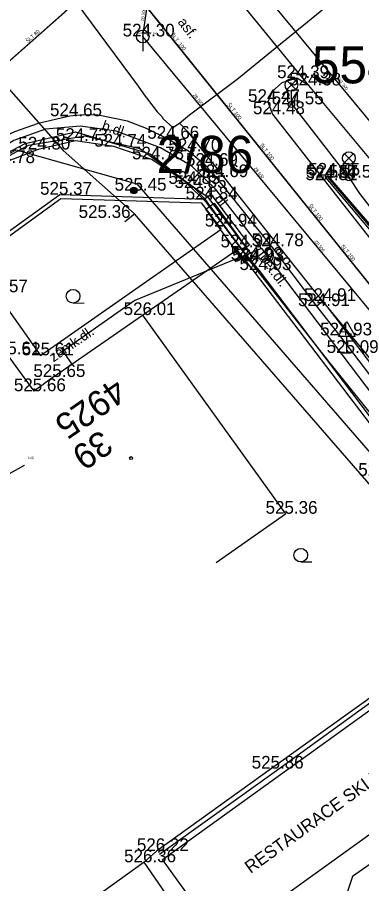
# Model space of a CAD drawing. Extents: x -668867 to -667827, y -1131943 to -1131019.
# Drawn here: x -668677.7 to -668657.4, y -1131290.2 to -1131239 of the extents above; entities that cross this region are included whole.
import ezdxf

# ---------------------------------------------------------------- set-up
doc = ezdxf.new("R2010")
doc.units = 0
for name, color, linetype in [('G_Bod_tecka', 7, 'Continuous'), ('G_Bod_vyska', 7, 'Continuous'), ('G_Budovy-znacky', 7, 'Continuous'), ('G_Budovy_Objekty', 7, 'Continuous'), ('G_Budovy_vstupy', 7, 'Continuous'), ('G_Cesty_Schody', 7, 'Continuous'), ('G_Cisla_orientacni', 7, 'Continuous'), ('G_Cisla_popisna', 7, 'Continuous'), ('G_Objekty_dopravni', 7, 'Continuous'), ('G_Objekty_technicke', 7, 'Continuous'), ('G_Plochy_zpevnene', 7, 'Continuous'), ('G_Ploty', 7, 'Continuous'), ('G_Ploty_vstupy', 7, 'Continuous'), ('G_Popisy_povrchu', 7, 'Continuous'), ('G_Poznamky_odkaz', 7, 'Continuous'), ('G_Site-kanalizace', 7, 'Continuous'), ('G_Site-Sloupy', 7, 'Continuous'), ('G_Z_CHRANICKA-TEPLOVOD_kotovane', 7, 'Continuous'), ('G_Z_ELsilove_podz_kotovane', 7, 'Continuous'), ('G_Z_ELsilove_zrusene', 7, 'Continuous'), ('G_Z_KANAL_podz_kotovane', 7, 'Continuous'), ('G_Z_KANAL_podz_priblizne', 7, 'Continuous'), ('G_Z_PLYNY_podz_geodeticky', 7, 'Continuous'), ('G_Z_SPOJE_podz_geodeticky', 7, 'Continuous'), ('G_Z_SPOJE_podz_kotovane', 7, 'Continuous'), ('G_Z_SPOJE_podz_priblizne', 7, 'Continuous'), ('G_Z_VODA_podz_kotovane', 7, 'Continuous'), ('G_Zabradli_Svodidla', 7, 'Continuous'), ('G_Zelen-Znacky', 7, 'Continuous'), ('Vrstva 1', 7, 'Continuous'), ('Vrstva 10', 7, 'Continuous'), ('Vrstva 12', 7, 'Continuous'), ('Vrstva 17', 7, 'Continuous'), ('Vrstva 2', 7, 'Continuous'), ('Vrstva 25', 7, 'Continuous'), ('Vrstva 26', 7, 'Continuous'), ('Vrstva 3', 7, 'Continuous'), ('Vrstva 4', 7, 'Continuous'), ('Vrstva 8', 7, 'Continuous')]:
    doc.layers.add(name, color=color, linetype=linetype)

msp = doc.modelspace()

# ---------------------------------------------------------------- linework, layer by layer
at = {"layer": 'G_Bod_tecka'}
for p, q in [((-668670.28, -1131240.15), (-668670.28, -1131240.15)), ((-668661.18, -1131242.61), (-668661.18, -1131242.61)), ((-668660.47, -1131243.04), (-668660.47, -1131243.04)), ((-668662.9, -1131244.02), (-668662.9, -1131244.02)), ((-668661.5, -1131244.16), (-668661.5, -1131244.16)), ((-668674.59, -1131244.86), (-668674.59, -1131244.86)), ((-668662.61, -1131244.74), (-668662.61, -1131244.74)), ((-668674.25, -1131246.32), (-668674.25, -1131246.32)), ((-668668.82, -1131246.19), (-668668.82, -1131246.19)), ((-668676.45, -1131246.83), (-668676.45, -1131246.83)), ((-668671.98, -1131246.66), (-668671.98, -1131246.66)), ((-668667.58, -1131246.93), (-668667.58, -1131246.93)), ((-668669.75, -1131247.41), (-668669.75, -1131247.41)), ((-668666.55, -1131247.79), (-668666.55, -1131247.79)), ((-668665.94, -1131248.46), (-668665.94, -1131248.46)), ((-668659.47, -1131248.5), (-668659.47, -1131248.5)), ((-668659.35, -1131248.37), (-668659.35, -1131248.37)), ((-668658.11, -1131248.49), (-668658.11, -1131248.49)), ((-668667.6, -1131248.86), (-668667.6, -1131248.86)), ((-668659.57, -1131248.64), (-668659.57, -1131248.64)), ((-668675.18, -1131249.5), (-668675.18, -1131249.5)), ((-668670.78, -1131249.26), (-668670.78, -1131249.26)), ((-668667.24, -1131249.1), (-668667.24, -1131249.1)), ((-668666.58, -1131249.78), (-668666.58, -1131249.78)), ((-668672.89, -1131250.87), (-668672.89, -1131250.87)), ((-668665.45, -1131251.38), (-668665.45, -1131251.38)), ((-668664.52, -1131252.61), (-668664.52, -1131252.61)), ((-668662.68, -1131252.54), (-668662.68, -1131252.54)), ((-668663.93, -1131253.35), (-668663.93, -1131253.35)), ((-668663.83, -1131253.44), (-668663.83, -1131253.44)), ((-668663.4, -1131253.95), (-668663.4, -1131253.95)), ((-668660.01, -1131256.08), (-668660.01, -1131256.08)), ((-668659.65, -1131255.78), (-668659.65, -1131255.78)), ((-668670.27, -1131256.61), (-668670.27, -1131256.61)), ((-668658.64, -1131257.81), (-668658.64, -1131257.81)), ((-668676.31, -1131258.99), (-668676.31, -1131258.99)), ((-668658.23, -1131258.85), (-668658.23, -1131258.85)), ((-668675.56, -1131260.27), (-668675.56, -1131260.27)), ((-668676.7, -1131261.11), (-668676.7, -1131261.11)), ((-668661.86, -1131268.35), (-668661.86, -1131268.35)), ((-668662.67, -1131283.41), (-668662.67, -1131283.41)), ((-668669.46, -1131288.28), (-668669.46, -1131288.28)), ((-668670.2, -1131288.94), (-668670.2, -1131288.94))]:
    msp.add_line(p, q, dxfattribs=at)
at = {"layer": 'G_Budovy-znacky'}
msp.add_circle((-668670.97, -1131265.061), 0.0875, dxfattribs=at)
at = {"layer": 'G_Budovy_Objekty'}
for p, q in [((-668675.56, -1131260.27), (-668670.3, -1131256.61)), ((-668670.3, -1131256.61), (-668661.86, -1131268.35)), ((-668676.7, -1131261.11), (-668678.28, -1131258.93)), ((-668665.94, -1131271.23), (-668661.86, -1131268.35)), ((-668669.11, -1131288.77), (-668652.01, -1131276.45)), ((-668649.65, -1131282.11), (-668665.63, -1131293.6)), ((-668670.2, -1131288.94), (-668673.43, -1131291.26)), ((-668667.36, -1131293.06), (-668670.2, -1131288.94)), ((-668666.2, -1131292.8), (-668669.11, -1131288.77))]:
    msp.add_line(p, q, dxfattribs=at)
at = {"layer": 'G_Budovy_vstupy'}
msp.add_line((-668675.56, -1131260.27), (-668676.7, -1131261.11), dxfattribs=at)
at = {"layer": 'G_Cesty_Schody'}
for p, q in [((-668660.47, -1131243.04), (-668676.96, -1131222.83)), ((-668666.55, -1131247.79), (-668667.6, -1131248.86)), ((-668662.68, -1131252.54), (-668663.83, -1131253.44)), ((-668659.65, -1131255.78), (-668660.01, -1131256.08))]:
    msp.add_line(p, q, dxfattribs=at)
msp.add_lwpolyline([(-668659.65, -1131255.78), (-668647.48, -1131271.71), (-668624, -1131302.71)], dxfattribs=at)
at = {"layer": 'G_Objekty_dopravni'}
for p, q in [((-668658.73, -1131257.85), (-668658.23, -1131257)), ((-668658.23, -1131257), (-668657.73, -1131257.85)), ((-668658.73, -1131257.85), (-668657.73, -1131257.85)), ((-668658.23, -1131258.85), (-668658.23, -1131257.85)), ((-668658.48, -1131258.85), (-668657.98, -1131258.85))]:
    msp.add_line(p, q, dxfattribs=at)
at = {"layer": 'G_Objekty_technicke'}
for p, q in [((-668661.765, -1131242.745), (-668661.235, -1131243.275)), ((-668661.765, -1131243.275), (-668661.235, -1131242.745)), ((-668661.5, -1131244.16), (-668661.5, -1131243.385)), ((-668658.375, -1131247.075), (-668657.845, -1131247.605)), ((-668658.375, -1131247.605), (-668657.845, -1131247.075)), ((-668658.11, -1131248.49), (-668658.11, -1131247.715))]:
    msp.add_line(p, q, dxfattribs=at)
for centre, radius in [((-668661.5, -1131243.01), 0.375), ((-668661.5, -1131244.16), 0.19), ((-668661.5, -1131244.16), 0.05), ((-668658.11, -1131247.34), 0.375), ((-668658.11, -1131248.49), 0.19), ((-668658.11, -1131248.49), 0.05)]:
    msp.add_circle(centre, radius, dxfattribs=at)
at = {"layer": 'G_Plochy_zpevnene'}
for p, q in [((-668659.47, -1131248.5), (-668659.57, -1131248.64)), ((-668659.47, -1131248.5), (-668651.37, -1131258.14)), ((-668659.57, -1131248.64), (-668656.1, -1131253.06)), ((-668670.3, -1131256.61), (-668664.72, -1131252.76))]:
    msp.add_line(p, q, dxfattribs=at)
for points in [[(-668660.47, -1131243.04), (-668661.18, -1131242.61), (-668662.06, -1131242.89), (-668662.63, -1131243.4), (-668662.9, -1131244.02), (-668662.61, -1131244.74), (-668659.57, -1131248.64)], [(-668656.04, -1131248.37), (-668660.47, -1131243.04)], [(-668674.59, -1131244.86), (-668676.45, -1131245.3), (-668677.86, -1131245.78), (-668679.91, -1131246.72), (-668681.77, -1131247.93), (-668682.93, -1131248.83)], [(-668665.94, -1131248.46), (-668666.55, -1131247.79), (-668667.58, -1131246.93), (-668668.82, -1131246.19), (-668670.05, -1131245.58), (-668671.19, -1131245.15), (-668672.91, -1131244.8), (-668673.76, -1131244.77), (-668674.59, -1131244.86)], [(-668674.25, -1131246.32), (-668676.45, -1131246.83), (-668678.55, -1131247.63), (-668680.81, -1131249.06), (-668681.77, -1131247.93)], [(-668666.58, -1131249.78), (-668667.24, -1131249.1), (-668667.6, -1131248.86), (-668669.75, -1131247.41), (-668671.98, -1131246.66), (-668674.25, -1131246.32)], [(-668662.68, -1131252.54), (-668665.94, -1131248.46)], [(-668659.35, -1131248.37), (-668659.47, -1131248.5)], [(-668651.07, -1131257.98), (-668659.35, -1131248.37)], [(-668676.31, -1131258.99), (-668665.65, -1131251.53)], [(-668658.64, -1131257.81), (-668660.01, -1131256.08), (-668662.68, -1131252.54)], [(-668681.68, -1131257.15), (-668678.97, -1131255.26), (-668676.31, -1131258.99)], [(-668633.58, -1131290.68), (-668658.64, -1131257.81)]]:
    msp.add_lwpolyline(points, dxfattribs=at)
at = {"layer": 'G_Ploty'}
for p, q in [((-668675.18, -1131249.5), (-668683.04, -1131255.19)), ((-668666.58, -1131249.78), (-668675.18, -1131249.5)), ((-668682.91, -1131255.37), (-668675.11, -1131249.72)), ((-668675.11, -1131249.72), (-668666.83, -1131249.97)), ((-668666.83, -1131249.97), (-668665.65, -1131251.53)), ((-668665.45, -1131251.38), (-668666.58, -1131249.78)), ((-668664.72, -1131252.76), (-668663.64, -1131254.14)), ((-668663.64, -1131254.14), (-668650.39, -1131271.57)), ((-668648.9, -1131273.5), (-668662.67, -1131283.41)), ((-668662.52, -1131283.61), (-668649.63, -1131274.28)), ((-668662.67, -1131283.41), (-668669.46, -1131288.28)), ((-668669.29, -1131288.47), (-668662.52, -1131283.61))]:
    msp.add_line(p, q, dxfattribs=at)
for points in [[(-668663.4, -1131253.95), (-668663.83, -1131253.44), (-668663.9, -1131253.35), (-668664.52, -1131252.61)], [(-668663.4, -1131253.95), (-668663.64, -1131254.14)], [(-668651.91, -1131269.15), (-668663.4, -1131253.95)]]:
    msp.add_lwpolyline(points, dxfattribs=at)
at = {"layer": 'G_Ploty_vstupy'}
for p, q in [((-668664.52, -1131252.61), (-668665.45, -1131251.38)), ((-668669.46, -1131288.28), (-668670.2, -1131288.94))]:
    msp.add_line(p, q, dxfattribs=at)
at = {"layer": 'G_Site-kanalizace'}
msp.add_line((-668670.28, -1131239.775), (-668670.28, -1131241.025), dxfattribs=at)
msp.add_circle((-668670.28, -1131240.15), 0.375, dxfattribs=at)
at = {"layer": 'G_Site-Sloupy'}
for radius in [0.2, 0.18, 0.16, 0.14, 0.12, 0.1, 0.08, 0.06, 0.04, 0.02]:
    msp.add_circle((-668670.81, -1131249.25), radius, dxfattribs=at)
at = {"layer": 'G_Z_CHRANICKA-TEPLOVOD_kotovane'}
for points in [[(-668666.659, -1131249.771), (-668666.261, -1131249.469), (-668663.981, -1131252.479), (-668664.167, -1131252.62), (-668664.379, -1131252.781), (-668666.34, -1131250.192)], [(-668666.34, -1131250.192), (-668666.065, -1131249.993), (-668664.167, -1131252.62), (-668663.784, -1131253.151), (-668664.27, -1131253.502), (-668666.552, -1131250.345)]]:
    msp.add_lwpolyline(points, close=True, dxfattribs=at)
at = {"layer": 'G_Z_ELsilove_podz_kotovane'}
for points in [[(-668613.41, -1131308.75), (-668627.16, -1131290.21), (-668626.62, -1131289.78), (-668627.25, -1131290.08), (-668635.78, -1131279.05), (-668635.2, -1131278.71), (-668635.51, -1131278.95), (-668638.68, -1131275.14), (-668642.06, -1131270.12), (-668644.05, -1131267.56), (-668648.26, -1131262.16), (-668651.5, -1131257.7), (-668652.12, -1131256.36), (-668652.76, -1131255.45), (-668655.53, -1131251.93), (-668657.47, -1131249.43), (-668658.07, -1131248.51), (-668658.21, -1131248.34), (-668661.39, -1131244.23), (-668661.5, -1131244.12)], [(-668702.765, -1131265.935), (-668703.529, -1131265.284), (-668703.603, -1131265.221), (-668703.41, -1131265.088), (-668698.8, -1131261.91), (-668690.9, -1131256.1), (-668690.3, -1131255.66), (-668685.32, -1131251.999), (-668684.75, -1131251.58), (-668680.73, -1131248.57), (-668680.193, -1131248.28), (-668677.03, -1131246.57), (-668673.71, -1131246.02), (-668672.62, -1131246.271), (-668670.45, -1131246.77), (-668670.112, -1131247.012), (-668667.886, -1131248.601), (-668666.46, -1131249.62), (-668664.18, -1131252.63), (-668664.364, -1131252.861), (-668664.831, -1131253.448)], [(-668664.831, -1131253.448), (-668664.192, -1131253.098), (-668663.974, -1131253.4), (-668659.321, -1131259.354), (-668654.844, -1131264.91), (-668650.886, -1131269.37), (-668650.812, -1131269.559), (-668650.21, -1131270.79)]]:
    msp.add_lwpolyline(points, dxfattribs=at)
at = {"layer": 'G_Z_ELsilove_zrusene'}
msp.add_lwpolyline([(-668679.045, -1131247.418), (-668677.23, -1131246.474), (-668674.251, -1131245.789), (-668672.62, -1131246.271), (-668670.112, -1131247.012), (-668669.843, -1131247.091), (-668667.933, -1131248.555), (-668667.886, -1131248.601), (-668666.322, -1131250.15), (-668664.364, -1131252.861), (-668664.192, -1131253.098)], dxfattribs=at)
msp.add_lwpolyline([(-668679.045, -1131247.418), (-668677.23, -1131246.474), (-668674.251, -1131245.789), (-668672.62, -1131246.271), (-668670.112, -1131247.012), (-668669.843, -1131247.091), (-668667.933, -1131248.555), (-668667.886, -1131248.601), (-668666.322, -1131250.15), (-668664.364, -1131252.861), (-668664.192, -1131253.098)], dxfattribs=at)
at = {"layer": 'G_Z_KANAL_podz_kotovane'}
for p, q in [((-668670.28, -1131240.15), (-668668.9, -1131230.6)), ((-668643.86, -1131272.07), (-668670.28, -1131240.15)), ((-668685.66, -1131270.16), (-668677.27, -1131265.47))]:
    msp.add_line(p, q, dxfattribs=at)
at = {"layer": 'G_Z_KANAL_podz_priblizne'}
msp.add_lwpolyline([(-668630.31, -1131277.23), (-668652.86, -1131249.99), (-668668.9, -1131230.6)], dxfattribs=at)
at = {"layer": 'G_Z_PLYNY_podz_geodeticky'}
for points in [[(-668670.07, -1131243.73), (-668670.01, -1131243.86), (-668669.42, -1131244.6), (-668669.16, -1131244.88), (-668669.07, -1131245.01), (-668668.51, -1131245.52), (-668668.12, -1131245.28), (-668667.52, -1131244.78), (-668664.71, -1131242.67), (-668656.404, -1131235.868), (-668656.37, -1131235.84), (-668655.7, -1131235.31), (-668655.39, -1131235.06)], [(-668670.07, -1131243.73), (-668670.54, -1131243.09), (-668676.08, -1131235.58), (-668676.22, -1131235.37)], [(-668668.12, -1131245.28), (-668667.66, -1131245.75), (-668660.13, -1131255.22), (-668654.02, -1131262.64), (-668646.38, -1131272.37), (-668640.53, -1131280.42), (-668625.57, -1131300.03), (-668616.54, -1131312.62), (-668608.03, -1131324.52), (-668599.32, -1131337.08), (-668595.28, -1131342.96), (-668595.11, -1131343.22), (-668594.9, -1131343.6), (-668594.55, -1131344.04)]]:
    msp.add_lwpolyline(points, dxfattribs=at)
at = {"layer": 'G_Z_SPOJE_podz_geodeticky'}
for points in [[(-668681.38, -1131228.99), (-668676.81, -1131234.75), (-668681.68, -1131238.75), (-668681.62, -1131239.38), (-668674.99, -1131246.88), (-668670.77, -1131250.62)], [(-668663.27, -1131252.68), (-668665.95, -1131249.21), (-668667.39, -1131247.82), (-668669.23, -1131246.73), (-668671.86, -1131245.75), (-668673.96, -1131245.44), (-668676.02, -1131245.63), (-668677.9, -1131246.29), (-668682.41, -1131249.11), (-668687.49, -1131253.47), (-668689.99, -1131255.51), (-668695.91, -1131260.34), (-668700.69, -1131264.03), (-668702.08, -1131265.1)], [(-668825.58, -1131277.708), (-668825.5, -1131282.5), (-668821.97, -1131284.49), (-668795.83, -1131284.18), (-668781.07, -1131283.62), (-668771.88, -1131282.6), (-668763.2, -1131281.22), (-668753.19, -1131279.08), (-668746.35, -1131277.14), (-668732.15, -1131272.3), (-668719.76, -1131266.87), (-668705.05, -1131257.72), (-668701.21, -1131263.15), (-668689.08, -1131254.94), (-668681, -1131248.57), (-668677.75, -1131246.85), (-668670.63, -1131248.85), (-668649.26, -1131273.52)], [(-668671.33, -1131251.08), (-668670.77, -1131250.62)], [(-668649.26, -1131273.52), (-668650.26, -1131274.24), (-668670.77, -1131250.62)], [(-668663.27, -1131252.68), (-668670.75, -1131255.75), (-668675, -1131258.75), (-668674.42, -1131259.57)], [(-668663.27, -1131252.68), (-668651.87, -1131267.73)], [(-668642.44, -1131280.7), (-668650.71, -1131284.76), (-668657.9, -1131289.78), (-668659.61, -1131294.97)]]:
    msp.add_lwpolyline(points, dxfattribs=at)
at = {"layer": 'G_Z_SPOJE_podz_kotovane'}
for points in [[(-668663.27, -1131252.68), (-668670.75, -1131255.75), (-668675, -1131258.75), (-668674.42, -1131259.57)], [(-668642.44, -1131280.7), (-668650.71, -1131284.76), (-668657.9, -1131289.78), (-668659.61, -1131294.97)]]:
    msp.add_lwpolyline(points, dxfattribs=at)
at = {"layer": 'G_Z_SPOJE_podz_priblizne'}
for points in [[(-668681.38, -1131228.99), (-668676.81, -1131234.75), (-668681.68, -1131238.75), (-668681.62, -1131239.38), (-668674.99, -1131246.88), (-668670.77, -1131250.62)], [(-668825.58, -1131277.708), (-668825.5, -1131282.5), (-668821.97, -1131284.49), (-668795.83, -1131284.18), (-668781.07, -1131283.62), (-668771.88, -1131282.6), (-668763.2, -1131281.22), (-668753.19, -1131279.08), (-668746.35, -1131277.14), (-668732.15, -1131272.3), (-668719.76, -1131266.87), (-668705.05, -1131257.72), (-668701.21, -1131263.15), (-668689.08, -1131254.94), (-668681, -1131248.57), (-668677.75, -1131246.85), (-668670.63, -1131248.85), (-668649.26, -1131273.52)], [(-668671.33, -1131251.08), (-668670.77, -1131250.62)], [(-668649.26, -1131273.52), (-668650.26, -1131274.24), (-668670.77, -1131250.62)], [(-668663.27, -1131252.68), (-668670.75, -1131255.75), (-668675, -1131258.75), (-668674.42, -1131259.57)], [(-668642.44, -1131280.7), (-668650.71, -1131284.76), (-668657.9, -1131289.78), (-668659.61, -1131294.97)]]:
    msp.add_lwpolyline(points, dxfattribs=at)
at = {"layer": 'G_Z_VODA_podz_kotovane'}
for points in [[(-668672.01, -1131235.96), (-668672.22, -1131236.13), (-668672.43, -1131236.29), (-668674.91, -1131238.73), (-668688.7, -1131250.9), (-668689.74, -1131251.7), (-668691.8, -1131253.28), (-668695.94, -1131256.47), (-668706.92, -1131264.91), (-668725.99, -1131274.18), (-668730.05, -1131275.55), (-668730.06, -1131275.55), (-668745.66, -1131279.72), (-668746.43, -1131279.98), (-668747.88, -1131280.36), (-668780.07, -1131288.82), (-668781.85, -1131289.49), (-668782.47, -1131289.67), (-668786.01, -1131289.94)], [(-668672.01, -1131235.96), (-668671.84, -1131236.17), (-668635.06, -1131281.98), (-668612.84, -1131311.89), (-668596.37, -1131335.83)]]:
    msp.add_lwpolyline(points, dxfattribs=at)
at = {"layer": 'G_Zabradli_Svodidla'}
msp.add_lwpolyline([(-668659.36, -1131248.48), (-668651.23, -1131258.01)], dxfattribs=at)
at = {"layer": 'G_Zelen-Znacky'}
for p, q in [((-668674.392, -1131255.9), (-668673.742, -1131255.897)), ((-668660.952, -1131271.2), (-668660.302, -1131271.197))]:
    msp.add_line(p, q, dxfattribs=at)
for centre in [(-668674.392, -1131255.496), (-668660.952, -1131270.797)]:
    msp.add_circle(centre, 0.403, dxfattribs=at)
at = {"layer": 'Vrstva 1'}
for p, q in [((-668661.5, -1131244.12), (-668661.5, -1131244.12)), ((-668658.21, -1131248.34), (-668658.21, -1131248.34)), ((-668670.81, -1131249.25), (-668670.81, -1131249.25))]:
    msp.add_line(p, q, dxfattribs=at)
at = {"layer": 'Vrstva 10'}
for p, q in [((-668670.28, -1131240.151), (-668668.897, -1131230.595)), ((-668643.856, -1131272.072), (-668670.28, -1131240.151))]:
    msp.add_line(p, q, dxfattribs=at)
at = {"layer": 'Vrstva 12'}
msp.add_line((-668685.66, -1131270.16), (-668677.27, -1131265.47), dxfattribs=at)
at = {"layer": 'Vrstva 17'}
for p, q in [((-668661.39, -1131244.23), (-668661.5, -1131244.12)), ((-668658.21, -1131248.34), (-668661.39, -1131244.23)), ((-668658.07, -1131248.51), (-668658.21, -1131248.34)), ((-668657.47, -1131249.43), (-668658.07, -1131248.51)), ((-668655.53, -1131251.93), (-668657.47, -1131249.43))]:
    msp.add_line(p, q, dxfattribs=at)
msp.add_lwpolyline([(-668630.31, -1131277.23), (-668652.86, -1131249.99), (-668668.897, -1131230.595)], dxfattribs=at)
at = {"layer": 'Vrstva 25'}
msp.add_lwpolyline([(-668672.011, -1131235.96), (-668671.843, -1131236.169), (-668635.055, -1131281.976), (-668612.843, -1131311.885), (-668596.37, -1131335.83)], dxfattribs=at)
at = {"layer": 'Vrstva 26'}
msp.add_lwpolyline([(-668672.011, -1131235.96), (-668672.219, -1131236.127), (-668672.428, -1131236.295), (-668674.912, -1131238.726), (-668688.701, -1131250.896), (-668689.742, -1131251.699), (-668691.8, -1131253.28), (-668695.943, -1131256.466), (-668706.92, -1131264.91), (-668725.992, -1131274.182), (-668730.05, -1131275.55), (-668730.063, -1131275.553), (-668745.656, -1131279.717), (-668746.431, -1131279.983), (-668747.882, -1131280.363), (-668780.073, -1131288.822), (-668781.85, -1131289.49), (-668782.472, -1131289.667), (-668786.009, -1131289.938)], dxfattribs=at)
at = {"layer": 'Vrstva 8'}
for p, q in [((-668670.28, -1131240.151), (-668670.28, -1131240.151)), ((-668677.27, -1131265.47), (-668677.27, -1131265.47))]:
    msp.add_line(p, q, dxfattribs=at)

# ---------------------------------------------------------------- texts
at = {"layer": 'G_Bod_vyska'}
for s, p in [('524.30', (-668671.466, -1131240.15)), ('524.39', (-668662.346, -1131242.61)), ('524.38', (-668661.634, -1131243.04)), ('524.47', (-668664.064, -1131244.02)), ('524.55', (-668662.664, -1131244.16)), ('524.65', (-668675.758, -1131244.86)), ('524.48', (-668663.774, -1131244.74)), ('524.66', (-668670.012, -1131246.19)), ('524.73', (-668675.414, -1131246.32)), ('524.74', (-668673.144, -1131246.66)), ('524.80', (-668677.626, -1131246.83)), ('524.70', (-668668.766, -1131246.93)), ('524.78', (-668679.714, -1131247.63)), ('524.78', (-668670.914, -1131247.41)), ('524.69', (-668667.73, -1131247.79)), ('524.69', (-668667.12, -1131248.46)), ('524.51', (-668660.672, -1131248.64)), ('524.57', (-668660.634, -1131248.5)), ('524.55', (-668660.514, -1131248.37)), ('524.50', (-668659.296, -1131248.49)), ('525.45', (-668671.944, -1131249.26)), ('524.85', (-668668.764, -1131248.86)), ('524.85', (-668668.404, -1131249.1)), ('525.37', (-668676.344, -1131249.5)), ('524.84', (-668667.744, -1131249.78)), ('525.36', (-668674.068, -1131250.87)), ('524.94', (-668666.616, -1131251.38)), ('524.94', (-668665.686, -1131252.61)), ('524.78', (-668663.844, -1131252.54)), ('524.93', (-668665.086, -1131253.35)), ('524.93', (-668664.996, -1131253.44)), ('524.93', (-668664.566, -1131253.95)), ('525.57', (-668680.134, -1131255.26)), ('524.91', (-668660.754, -1131255.78)), ('524.91', (-668661.114, -1131256.08)), ('526.01', (-668671.408, -1131256.61)), ('524.93', (-668659.806, -1131257.81)), ('525.61', (-668679.396, -1131258.93)), ('525.61', (-668677.426, -1131258.99)), ('525.09', (-668659.418, -1131258.85)), ('525.65', (-668676.738, -1131260.27)), ('525.66', (-668677.892, -1131261.11)), ('525.85', (-668657.554, -1131266.11)), ('525.36', (-668663.028, -1131268.35)), ('525.86', (-668663.848, -1131283.41)), ('526.22', (-668670.628, -1131288.28)), ('526.36', (-668671.382, -1131288.94))]:
    msp.add_text(s, height=0.75, dxfattribs=at).set_placement(p)
at = {"layer": 'G_Cisla_orientacni'}
msp.add_text('39', height=1.5, rotation=214.5998, dxfattribs=at).set_placement((-668672.747, -1131263.342))
at = {"layer": 'G_Cisla_popisna'}
msp.add_text('4925', height=1.5, rotation=214.5998, dxfattribs=at).set_placement((-668671.929, -1131260.258))
at = {"layer": 'G_Popisy_povrchu'}
for s, rotation, p in [('asf.', 307.4271, (-668668.247, -1131239.31)), ('b.dl.', 341.3106, (-668672.747, -1131245.658)), ('z.dl.', 308.4672, (-668666.474, -1131249.278)), ('bet.dl.', 307.0997, (-668663.446, -1131253.259)), ('zamk.dl.', 34.5998, (-668675.551, -1131259.41))]:
    msp.add_text(s, height=0.6, rotation=rotation, dxfattribs=at).set_placement(p)
at = {"layer": 'G_Poznamky_odkaz'}
msp.add_text('RESTAURACE SKLENÍK', height=0.75, rotation=35.7953, dxfattribs=at).set_placement((-668663.915, -1131289.636))
at = {"layer": 'Vrstva 2'}
for s, height, p in [('524.6 (522.16)', 0.13163, (-668670.619, -1131240.029)), ('0 (0)', 0.1316, (-668677.064, -1131265.117))]:
    msp.add_text(s, height=height, dxfattribs=at).set_placement(p)
at = {"layer": 'Vrstva 3'}
for s, rotation, p in [('ZB 500', 81.7752, (-668670.224, -1131239.268)), ('BET 300', 309.5934, (-668658.866, -1131242.607)), ('ZB 500', 309.6419, (-668667.316, -1131243.622)), ('ZB 500', 309.5978, (-668663.732, -1131247.951)), ('ZB 500', 309.6107, (-668660.148, -1131252.281))]:
    msp.add_text(s, height=0.1755, rotation=rotation, dxfattribs=at).set_placement(p)
at = {"layer": 'Vrstva 4'}
for s, rotation, p in [('ŠLT 80', 41.4544, (-668677.07, -1131240.537)), ('ŠLT  100', 308.7463, (-668668.64, -1131240.043)), ('ŠLT 100', 308.7584, (-668665.309, -1131244.192)), ('ŠLT 100', 308.7584, (-668663.39, -1131246.581)), ('ŠLT 100', 308.7808, (-668660.512, -1131250.165)), ('ŠLT 100', 308.7674, (-668658.593, -1131252.553))]:
    msp.add_text(s, height=0.2194, rotation=rotation, dxfattribs=at).set_placement(p)
for s, p in [('5547', (-668660.297, -1131242.919)), ('2/86', (-668669.462, -1131248.216))]:
    msp.add_text(s, height=2.1939, dxfattribs=at).set_placement(p)

doc.saveas('drawing.dxf')
